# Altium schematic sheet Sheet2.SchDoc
size A4; DocumentNumber: 2; SheetNumber: 2; SheetTotal: 2
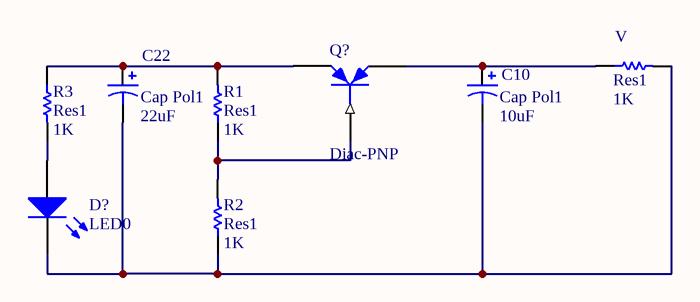
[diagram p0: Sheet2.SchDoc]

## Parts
C10  Cap Pol1  value 10uF  [RB7.6-15]
C22  Cap Pol1  value 22uF  [RB7.6-15]
D?  LED0  [LED-0]
Q?  Diac-PNP  [SOT89M]
R1  Res1  value 1K  [AXIAL-0.3]
R2  Res1  value 1K  [AXIAL-0.3]
R3  Res1  value 1K  [AXIAL-0.3]
V  Res1  value 1K  [AXIAL-0.3]

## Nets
NetC10_1: C10.1 Q?.3(C) V.1
NetC10_2: C10.2 C22.2 D?.2(K) R2.1 V.2
NetC22_1: C22.1 Q?.2(E) R1.2 R3.1
NetD?_1: D?.1(A) R3.2
NetQ?_1: Q?.1(B) R1.1 R2.2

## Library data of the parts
C10 C22 = Cap Pol1: Polarized Capacitor (Radial)
D? = LED0: Typical INFRARED GaAs LED
Q? = Diac-PNP: DIAC
R1-R3 V = Res1: Resistor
